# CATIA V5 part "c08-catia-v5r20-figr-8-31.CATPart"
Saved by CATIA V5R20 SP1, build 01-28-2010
Part number: Part1
Bounding box of the stored display mesh (mm): x -50 to 50, y -75 to 125, z 0 to 40
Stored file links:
  D:\v5_r20\psrt_files_downloaded\c08-catia-v5r20-prt\c08-catia-v5r20-figr-8-31.CATPart
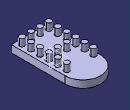
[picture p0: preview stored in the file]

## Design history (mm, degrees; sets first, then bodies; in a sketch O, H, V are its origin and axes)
Body1 (main body)
  Sketch1 on xy-plane, origin (0, 0, 0), H (1, 0, 0), V (0, 1, 0)
    line L1 (50, 75) -> (50, -75)
    line L2 (50, -75) -> (-50, -75)
    line L3 (-50, -75) -> (-50, 75)
    arc A1 centre (0, 75) radius 50 from (-50, 75) to (50, 75) cw
    point P5 (0, 75)
    axis line L4 (50, -75) -> (-50, 75)
    length L2 = 100
    distance P5 L2 = 150
    horizontal: L2 H
    vertical: L1 V, L3 V
    tangency: A1 L3, A1 L1
    midpoint: O L4
  Pad1: profile Sketch1, direction (0, 0, 1), length 20
  Sketch2 on face of Pad1, origin (0, 0, 20), H (1, 0, 0), V (0, 1, 0)
    circle A1 centre (35, -60) radius 7.5
    point P1 (35, -60)
    reference projected line E1 (-50, -75) -> (50, -75) from edge [face of Pad1 | face of Pad1]
    reference projected line E2 (50, -75) -> (50, 75) from edge [face of Pad1 | face of Pad1]
    distance P1 E1 = 15
    distance P1 E2 = 15
    radius A1 = 7.5
  Pad2: profile Sketch2, direction (0, 0, 1), length 20
  RectPattern1: of Pad2, direction 1 instances 4, spacing 25, along edge [face of Pad1 | face of Pad1] reversed, direction 2 instances 6, spacing 25, along edge [face of Pad1 | face of Pad1]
